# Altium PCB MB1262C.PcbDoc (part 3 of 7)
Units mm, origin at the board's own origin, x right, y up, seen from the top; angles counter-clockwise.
Board outline 208 x 250 mm, 6 copper layers (Top Layer, Layer 2, Layer 3, Layer 4, Layer 5, Bottom Layer), stack 1.596 mm thick; 483 components, 502 nets, 2134 pads, 1709 vias.
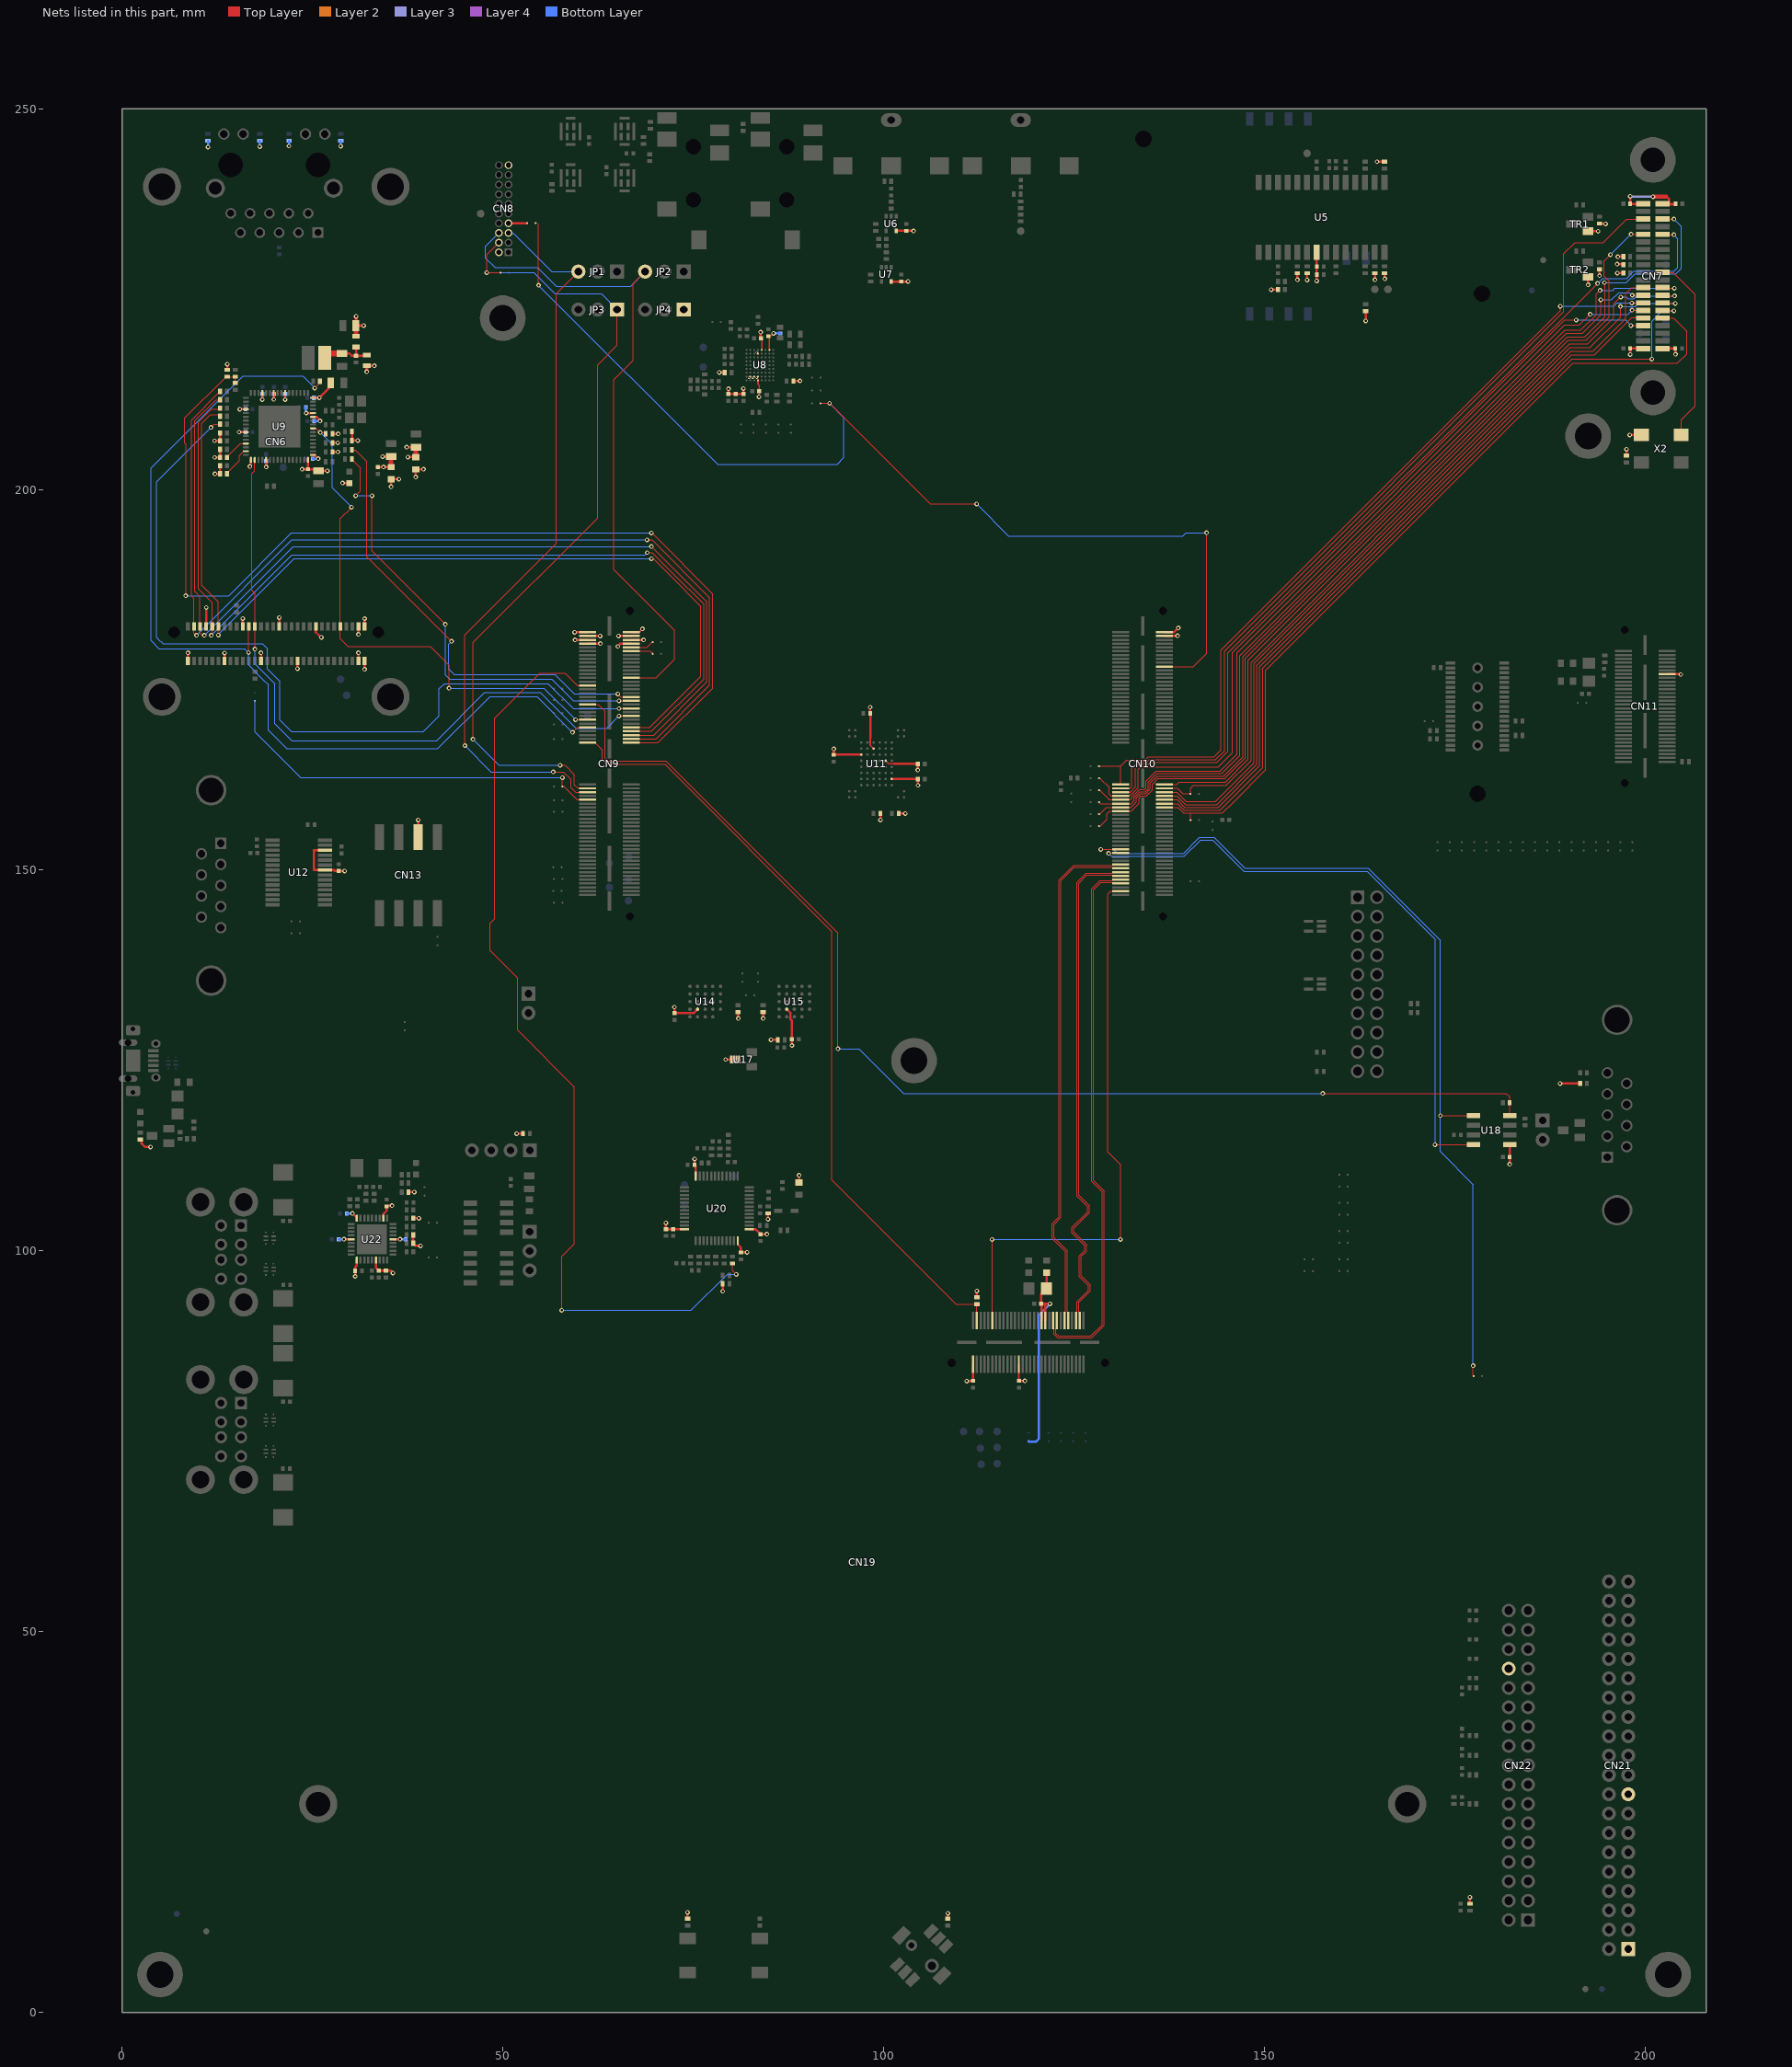
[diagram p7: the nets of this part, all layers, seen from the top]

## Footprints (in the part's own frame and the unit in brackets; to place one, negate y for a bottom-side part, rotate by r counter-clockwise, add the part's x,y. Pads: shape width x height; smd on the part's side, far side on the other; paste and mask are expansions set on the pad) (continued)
MIC_HCLGA_3X4X1_4LD [mm]
  rect 0.4x0.95 smd paste+0 mask+0.05: 1(0.45,-0.675) 2(0.45,0.675) 3(-0.45,0.675) 4(-0.45,-0.675)
  rect 1.3x0.35 smd paste+0 mask+0.05: 5(0,-1.725) 6(0,1.725)
  rect 0.35x2.3 smd paste+0 mask+0.05: 7(1.225,0) 8(-1.225,0)
  silkscreen extent -1.55,-2.05 1.55,2.05, body extent -1.45,-1.95 1.45,1.95, height 1.03
MIRE_PLACE_SMD_0P8MM [mm]
  round 0.8 smd mask+0.2: 1(0,0)
  Top Layer keep-out circle w0.01: c0,0 r0.804
MOD_MB1263 [mm]
  silkscreen extent -55,-8 65,78, body extent -55,-8 65,78, height 9.8
MOS_SOT23 [mm]
  rect 1x1.4 smd mask+0.05: 1(-0.95,-1.1) 2(0.95,-1.1) 3(0,1.1)
  silkscreen extent -1.63,-0.82 1.63,0.82, body extent -1.56,-1.25 1.56,1.25, height 1.1
NPN_SOT23 [mm]
  rect 1x1.4 smd mask+0.05: 1(-0.95,-1.1) 2(0.95,-1.1) 3(0,1.1)
  silkscreen extent -1.63,-0.82 1.63,0.82, body extent -1.56,-1.25 1.56,1.25, height 1.1
OSC_PLE_SM77H-SERIES_7X5_H1P73_4P [mm]
  rect 1.96x1.6 smd mask+0.05: 1(-2.62,-1.8) 2(2.62,-1.8) 3(2.62,1.8) 4(-2.62,1.8)
  silkscreen extent -3.55,-2.55 3.55,2.55, body extent -3.55,-2.55 3.55,2.55, height 2.17
PTH_M1261-3005-N_3P5X6_M3_H14 [mm]
  round 6 hole 3.5 mask+0.05: 1(0,0)
  silkscreen extent -3.25,-3.25 3.25,3.25, body extent -2.5,-2.5 2.5,2.5, height 14
R0402 [mm]
  rect 0.51x0.7 smd mask+0.05: 1(-0.45,0) 2(0.45,0)
  silkscreen extent -0.72,-0.43 0.72,0.43, body extent -0.52,-0.3 0.52,0.3, height 0.4
R0603 [mm]
  rect 0.64x1 smd mask+0.05: 1(-0.7,0) 2(0.7,0)
  silkscreen extent -1.05,-0.58 1.05,0.58, body extent -0.9,-0.5 0.9,0.5, height 0.56
SOLDER-BRIDGE_R0603-0R [mil]
  round 10 smd: 1(-19.68,0) 2(23.62,0)
  Top Layer region: -47.24,-19.68 -47.24,19.69 -15.75,19.69 3.94,0 -15.75,-19.68 -47.24,-19.68
  Top Layer region: -5.91,19.69 13.78,0 -5.91,-19.68 47.24,-19.68 47.24,19.69 -5.91,19.69
  silkscreen extent -50,-23 50,23, body extent -36,-20 36,20, height 22
SWI_WEALTHMETAL_TD-0341_4P [mm]
  rect 1.52x2.16 smd mask+0.05: 1(-2.25,-4.75) 2(-2.25,4.75) 3(2.25,-4.75) 4(2.25,4.75)
  silkscreen extent -3,-3.5 3,3.5, body extent -3,-5.15 3,5.15, height 7.55
SWI_XIEJIA_MT-008A_6P [mm]
  rect 1.8x1.1 smd mask+0.05: 1(-3.1,1.4) 2(-3.1,0) 3(-3.1,-1.4) 4(3.1,1.4) 5(3.1,0) 6(3.1,-1.4)
  rect 2.2x1.4 smd mask+0.05: 7(0,3.75) 8(0,-3.75)
  round 1.5 hole 0.8 unplated mask+0.05: MT1(0,1.9)
  round 1.8 hole 1.1 unplated mask+0.05: MT2(0,-1.9)
  silkscreen extent -3.7,-3.7 3.7,3.7, body extent -3.85,-3.75 3.85,3.75, height 5.2
TP_SMD_1MM [mm]
  round 1 smd mask+0.05: 1(0,0)
  silkscreen extent -0.7,-0.7 0.7,0.7

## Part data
B1: library part MT-008A_M, "Joystick with Hat, Multi Function Switch", Manuf_1="XIEJIA Electronics", Manuf_Part_1=MT-008A
B2: library part SW-PUSH-CMS_BLACK, "Non-Open Push-Button 0.1A 24V", Manuf_1=wealthmetal, Manuf_2=FARNELL, Manuf_Part_1=TD0341X-G01-BLA, Manuf_Part_2=535-930
C1 C2 C4 C5 C6 C7 C8 C9 C11 C12 C13 C15 C16 C18 C25 C27 C29 C30 C33 C34 C36 C40 C43 C49 C50 C53 C55 C56 C57 C58 C61 C62 C63 C64 C65 C66 C67 C70 C71 C72 C73 C74 C75 C78 C82 C83 C84 C87 C88 C89 C90 C91 C92 C93 C94 C95 C96 C99 C101 C103 C104 C105 C106 C113 C117 C119 C120 C121 C122 C123 C124 C125 C126 C127 C128 C129 C130 C131 C132 C133 C134: library part Cap_100nF_X7R_10%_0402, "Capacitor,100nF,16V,X7R,10%,0402,YAGEO", Manuf_1=YAGEO, Manuf_Part_1=CC0402KRX7R7BB104
C3 C17 C23 C24 C31 C35 C38 C39 C41 C97: library part Cap_4.7uF_X5R_20%_6V3_0402, "Capacitor MLCC 4,7µF 20% 6,3V 1,9uF@3,3V X5R 0402", Manuf_1=MURATA, Manuf_Part_1=GRM155R60J475ME87
C10 C14: library part Cap_22nF_X7R_10%_0402, "Capacitor,22nF,16V,X7R,10%,0402,YAGEO", Manuf_1=YAGEO, Manuf_Part_1=CC0402KRX7R7BB223
C19 C21 C42 C44: library part Cap_1uF_X5R_10%_6V3_0402, "Capacitor MLCC 1µF 10% 6,3V 0,4uF@3,3V X5R 0402 MURATA", Manuf_1=MURATA, Manuf_Part_1=GRM155R60J105KE19
C20 C32 C37 C47 C48 C51: library part Cap_22uF_X5R_20%_0805, "Capacitor,22uF,6.3V,X5R,20%,0805,Murata", Manuf_1=MURATA, Manuf_Part_1=GRM21BR60J226ME39L
C22 C26 C28: library part Cap_2.2uF_X5R_10%_0603, "Capacitor,2.2uF,10V, X5R,10%,0603,YAGEO", Manuf_1=YAGEO, Manuf_2=KEMET, Manuf_Part_1=CC0603KRX5R6BB225, Manuf_Part_2=C0603C225K8PACTU
C45 C46: library part Cap_10pF_NPO_5%_0402, "Capacitor,10pF,50V,NPO,5%,0402,YAGEO", Manuf_1=YAGEO, Manuf_Part_1=CC0402JRNPO9BN100
C52 C98: library part Cap_10uF_POL_10%_16V_1206, "Polarized Capacitor,10uF,16V,10%,typeA,AVX", Manuf_1=AVX, Manuf_Part_1=TAJA106K016R
C54 C85 C86: library part Cap_10nF_X7R_10%_0402, "Capacitor,10nF,16V,X7R,10%,0402,YAGEO", Manuf_1=YAGEO, Manuf_Part_1=CC0402KRX7R7BB103
C59: library part Cap_10nF_X7R_10%_0402_1, "Capacitor,10nF,16V,X7R,10%,0402,YAGEO", Manuf_1=YAGEO, Manuf_Part_1=CC0402KRX7R7BB103
C60 C108 C109 C110 C111 C112 C114 C115 C116: library part Cap_100pF_NPO_5%_0402, "Capacitor,100pF,50V,NPO,5%,0402,YAGEO", Manuf_1=YAGEO, Manuf_Part_1=CC0402JRNPO9BN101
C68: library part MCD-00011, "Capacitor, MLCC, 10nF, 16V, X7R, 10%, 0402, T=0.5mm", Manufacturer=YAGEO, Manufacturer_Part_Number=CC0402KRX7R7BB103, Package=C0402
C69: library part Cap_4.7uF_POL_10%_TANA, "Polarized Capacitor,4.7uF,16V,10%,typeA,AVX", Manuf_1=AVX, Manuf_Part_1=TAJA475K016R
C76 C100 C102 C107: library part Cap_220uF_POL_10%_TAJA, "Polarized Capacitor,220uF,10V,10%,AVX", Manuf_1=AVX, Manuf_Part_1=TAJC227K010R
C77: library part Cap_47uF_X5R_20%_0805, "Capacitor,47uF,10V,X5R,20%,0805,MURATA", Manuf_1=MURATA, Manuf_Part_1=GRM21BR61A476ME15K
C79: library part MCD-00095, "Capacitor, MLCC, 1uF, 6V3, X5R, 10%, 0402, T=0,5mm", Manufacturer=MURATA, Manufacturer_Part_Number=GRM155R60J105KE19, Package=C0402
C80 C81: library part Cap_18pF_NPO_5%_0402, "Capacitor,18pF,50V,NPO,5%,0402,YAGEO", Manuf_1=YAGEO, Manuf_Part_1=CC0402JRNPO9BN180
C118: library part Cap_1nF_X7R_10%_0402, "Capacitor,1nF,16V,X7R,10%,0402,YAGEO", Manuf_1=YAGEO, Manuf_Part_1=CC0402KRX7R7BB102
CN1: library part RCJ-013-SMT, "RCA Phono Jack, Right Angle, SMD, White", Manuf_1=JIUBABA, Manuf_2="CUI Inc", Manuf_Part_1=JBB0819100004
CN2: library part RCJ-014-SMT, "RCA Phono Jack, Right Angle, SMD, Yellow", Manuf_1=JIUBABA, Manuf_2="CUI Inc", Manuf_Part_1=JBB0819100002
CN3: library part CON_RJ45_48F_01GYDXNL, "RJ45 (shielded) Ethernet connector with Integral LEDs (green/yellow)", Manuf_1="Yuan Dean Scientific Co Ltd", Manuf_Part_1=48F-01GYDXNL
CN4: library part PJ3028B-3_GR, "Connector Jack Stereo 3.5mm, female SMT, Green (Line output)", Manuf_Part_2=PJ30280-3_GR
CN5: library part PJ3028B-3_GR, "Headset Connector Stereo 3.5mm, female SMT, black", Manuf_Part_1="PJ-3028B-3 4P"
CN6: library part CONN_ERF8_030, "RJ45 (shielded) Ethernet connector with Integral LEDs (green/yellow)", Manuf_1=SAMTEC, Manuf_Part_1=ERF8-30-07.0-L-DV-TR
CN7: library part CLM-120-02-L-D_2_Reverse_for_camera, "Header, 20-Pin, Dual row", Manuf_1=SAMTEC, Manuf_Part_1=CLM-120-02-L-D
CN8: library part "Header 10X2 TH VT 1.27mm_with MB1299", "20 Position Receptacle Connector 0.050\" (1.27mm) Through Hole Vertical Mount", Manuf_1=AMPHEMOL_FCI, Manuf_Part_1=20021311-00020T4LF
CN9 CN10: library part QSH-060-01-L-D-A, "Samtec connector QSH 120p", Manuf_1=SAMTEC
CN11: library part QSH-030-01-F-D-A, "HIGH SPEED SOCKET STRIP, .5mm PITCH, 60 PINS", Manuf_1=SAMTEC
CN12 CN15: library part CONN_DB9_male_3_1634580_2, "9 Positions,,through-hole , Right Angle, Product Series = HD 20, With Mating Connector LockMale", Manuf_1=TYCO, Manuf_Part_1=3-1634580-2
CN13: library part SSM-104-L-DH, "Série SSM, 8 Contact, 2.54 mm, CMS", Manuf_1=SAMTEC
CN14: library part CONN_Header_2x10_Male_JTAG, "Headers 2x10pins CH87 series 2.54mm Male", Manuf_1=CVILUX, Manuf_Part_1=CH87-20-2-V-1-00
CN16: library part 475900001, "USB-MICRO-AB, 47590-0001, SMT, MOLEX", Manuf_1=MOLEX, Manuf_Part_1=47590-0001
CN17: library part "Header 4", "Header, 4-Pin", Manuf_1=Samtec, Manuf_Part_1=TSW-104-07-x-S
CN18 CN20: library part CONN_USB_DUAL_TYPEA, "USB Dual Type A Receptacle 5600 Series.", Manuf_1=CONEXCON, Manuf_2=Cliff, Manuf_Part_1="5600 - 3081", Manuf_Part_2=FCK002A
CN19: library part QSH-030-01-F-D-A_DSI_LCD, "HIGH SPEED SOCKET STRIP, .5mm PITCH, 60 PINS", Manuf_1=SAMTEC, Manuf_Part_1=QSH-030-01-F-D-A
CN21: library part "Header 20x2 male", "Header,20 pin , Dual Row", Manuf_1=Samtec, Manuf_Part_1=TSW-120-07-G-D
CN22: library part MotorControl_connector, "Motor Control connector WINPIN", Manuf_1=WINPIN, Manuf_Part_1=BHFS03-34G01BT1
CN23: library part Smart_card_CN, "Smartcard connector"
D1: library part BAT60JFILM, "BAT60JFILM", Manuf_1=STM
H1 H2 H3 H4 H5: library part "POSITION HOLE C6D3R5"
JP1 JP2 JP3 JP4 JP7: library part "Header 3", "Header, 3-Pin", Manuf_1=Samtec, Manuf_Part_1=TSW-103-07-F-S
JP5 JP6: library part TSW-102-07-x-S, "Connector jumper 1 position", Manuf_1=SAMTEC, Manuf_2=KONTEC, Manuf_Part_2=4711955140470
L1 L2: library part BEAD_100R_2A_0603, "Bead,100R at 100Mhz,2A,0603", Manuf_1=MURATA, Manuf_Part_1=BLM18EG101TN1
L3 L4 L6 L8 L9: library part BEAD_600R_350MA_0603, "Bead,600R,350mA,0603", Manuf_1=Tai-tech, Manuf_2=TDK, Manuf_3=MURATA, Manuf_Part_1=FCM1608KF-601T03, Manuf_Part_2=MPZ1608S300A, Manuf_Part_3=BLM18PG121SN1D
L5: library part BEAD_120R_2A_0603, "Bead,120R at 100Mhz,2A,0603", Manuf_1=MURATA, Manuf_Part_1=BLM18PG121SN1D
L7: library part BEAD_26R_6A_0603_1, "Bead,26R at 100Mhz,6A,0603", Manuf_1=MURATA, Manuf_Part_1=BLM18KG260TN1
LD1: library part LED_green, "LED, Green, 0603", Manuf_1=everlight, Manuf_Part_1=19-213SYGC/S530-E2/TR8
LD2: library part LED_green, "LED, Green", Manuf_1=everlight, Manuf_Part_1=19-213SYGC/S530-E2/TR8
LD3: library part LED_red, "LED, Red, 0603", Manuf_1=everlight, Manuf_Part_1=19-213-R6C-AP1Q2B/3T
LE1: library part Ind_4.7uH_1A_30%, "FIXED IND 4.7UH 1A 180 MOHM 30% SMD", Manuf_1=MURATA, Manuf_Part_1=LQH32PN4R7NN0L
R1 R4 R13 R16 R25 R45 R49 R50 R53 R54 R56 R65 R69 R73 R74 R75 R76 R77 R82 R83 R93 R97 R99 R103 R104 R110 R111 R118 R122 R123 R124 R125 R127 R131 R132 R133 R134 R136: library part Res_0_5%_0402, "Resistor,0R,0402,5%,YAGEO", Manuf_1=YAGEO, Manuf_Part_1=RC0402JR-070RL
R2 R12 R17 R21 R28 R41 R43 R47 R94 R107 R129: library part Res_1K_1%_0402, "Resistor,1K,0402,1%,YAGEO", Manuf_1=YAGEO, Manuf_Part_1=RC0402FR-071KL
R3 R8 R19 R26 R27 R30 R31 R67 R78 R79 R80 R81 R84 R85 R86 R87 R88 R89 R91 R92 R95 R98 R101 R105 R109 R113 R128 R130 R139: library part Res_10K_1%_0402, "Resistor,10K,0402,1%,YAGEO", Manuf_1=YAGEO, Manuf_Part_1=RC0402FR-0710KL
R5 R22 R23 R24 R32 R108 R114 R115 R117 R119 R120 R121 R135: library part Res_100K_1%_0402, "Resistor,100K,0402,1%,YAGEO", Manuf_1=YAGEO, Manuf_Part_1=RC0402FR-07100KL, Manuf_Part_2=RT0402FRE07100KL
R6 R14 R20 R38 R39 R40 R58 R59 R61 R62 R64 R68 R71 R72 R141 R142: library part Res_4K7_1%_0402, "Resistor,4K7,0402,1%,YAGEO", Manuf_1=YAGEO, Manuf_Part_1=RC0402FR-074K7L, Manuf_Part_2=RT0402FRE074K7L
R7: library part Res_75_1%_0402, "Resistor,75,0402,1%,YAGEO", Manuf_1=YAGEO, Manuf_Part_1=RC0402FR-0775RL
R9: library part Res_110_1%_0402, "Resistor,110R,0402,1%,YAGEO", Manuf_1=YAGEO, Manuf_Part_1=RC0402FR-07110RL
R10: library part Res_210_1%_0402, "Resistor,210R,0402,1%,YAGEO", Manuf_1=YAGEO, Manuf_Part_1=RC0402FR-07210RL
R11 R18 R106 R138: library part Res_100_1%_0402, "Resistor,100R,0402,1%,YAGEO", Manuf_1=YAGEO, Manuf_Part_1=RC0402FR-07100RL
R15 R29: library part Res_1M_1%_0402, "Resistor,1M,0402,1%,YAGEO", Manuf_1=YAGEO, Manuf_Part_1=RC0402FR-071ML
R33 R34: library part Res_0_5%_0603, "Resistor,0R,0603,5%,YAGEO", Manuf_1=YAGEO, Manuf_Part_1=RC0603JR-070RL
R35: library part Res_2K2_1%_0402, "Resistor,2K2,0402,1%,YAGEO", Manuf_1=YAGEO, Manuf_Part_1=RC0402FR-072K2L
R36 R37: library part Res_20_1%_0402, "Resistor,20R,0402,1%,YAGEO", Manuf_1=YAGEO, Manuf_Part_1=RC0402FR-0720RL
R42 R46: library part Res_180_1%_0402_1, "Resistor,180R,0402,1%,YAGEO", Manuf_1=YAGEO, Manuf_Part_1=RC0402FR-07180RL
R44 R48 R51 R52 R55: library part Res_22_1%_0402, "Resistor,22R,0402,1%,YAGEO", Manuf_1=YAGEO, Manuf_Part_1=RC0402FR-0722RL
R57: library part Res_2K49_1%_0402, "Resistor,2K49,0402,1%,YAGEO", Manuf_1=YAGEO, Manuf_Part_1=RC0402FR-072K49L
R60 R63 R66: library part Res_1K5_1%_0402, "Resistor,1K5,0402,1%,YAGEO", Manuf_1=YAGEO, Manuf_Part_1=RC0402FR-071K5L
R70 R126 R140 R143: library part Res_510_1%_0402, "Resistor,510R,0402,1%,YAGEO", Manuf_1=YAGEO, Manuf_Part_1=RC0402FR-07510RL
R90: library part MCD-00285, "Resistor,15K,0402,5%,1/16W", Manufacturer=YAGEO, Manufacturer_Part_Number=RC0402JR-0715KL, Package=R0402
R96: library part Res_120_1%_0402, "Resistor,120R,0402,1%,YAGEO", Manuf_1=YAGEO, Manuf_Part_1=RC0402FR-07120RL
R100: library part Res_330_1%_0402, "Resistor,330R,0402,1%,YAGEO", Manuf_1=YAGEO, Manuf_Part_1=RC0402FR-07330RL
R102 R116: library part Res_47K_1%_0402, "Resistor,47K,0402,1%,YAGEO", Manuf_1=YAGEO, Manuf_Part_1=RC0402FR-0747KL
R112: library part Res_12K_1%_0402, "Resistor,12K,0402,1%,YAGEO", Manuf_1=YAGEO, Manuf_Part_1=9C06031A1202FKHFT
R137: library part Res_3K3_1%_0402, "Resistor,3K3,0402,1%,YAGEO", Manuf_1=YAGEO, Manuf_Part_1=RC0402FR-073K3L
SB1 SB4 SB12 SB13 SB14 SB18 SB19 SB20 SB21 SB22 SB23 SB24 SB25 SB26 SB28 SB29 SB30 SB31 SB32 SB33 SB52 SB53 SB55 SB56 SB58 SB61 SB63 SB65 SB66 SB67 SB68 SB69 SB70 SB71 SB72 SB73 SB74 SB75 SB76: library part SB_OFF, "Solder Bridge OFF"
SB2 SB3 SB5 SB6 SB7 SB8 SB9 SB10 SB11 SB15 SB16 SB17 SB27 SB34 SB35 SB36 SB37 SB38 SB39 SB40 SB41 SB42 SB43 SB44 SB45 SB46 SB47 SB48 SB49 SB50 SB51 SB54 SB57 SB59 SB60 SB62 SB77 SB78 SB79 SB80 SB81 SB82: library part SB_ON, "Solder Bridge ON"
SB64: library part MCD-00071, "Solder Bridge ON"
T1: library part 9013-SOT23, "NPN Bipolar Transistor", Manuf_1=NXP, Manuf_Part_1=BSR14
TP1 TP2 TP3 TP4 TP5 TP6 TP7 TP8 TP9 TP10 TP11 TP12 TP13 TP14 TP15 TP16 TP17 TP18 TP19 TP20 TP21 TP22 TP23 TP24 TP25 TP26 TP27 TP28 TP29 TP30: library part "TP 1mm", "Test Point"
TR1 TR2: library part BSN20, "N-channel enhancement mode field-effect transistor", Manuf_1=NXP, Manuf_2=DiodesINc, Manuf_Part_2=BSN20-7
U1 U2 U3 U4: library part MP34DT01TR-M, "MEMS audio sensor, omnidirectional digital microphone", Manuf_1=STM
U5: library part ST8024CDR, "Smartcard interface", Manuf_1=ST
U6 U7: library part 74LVC1G04SE, "Single inverter gate with a standard push-pull output. (1.65V to 5.5V)", Manuf_1="DIODES INC", Manuf_Part_1=74LVC1G04SE-7
U8: library part WM8994ECS/R, "Multi-Channel Audio Hub CODEC for Smartphones", Manuf_1="Cirrus Logic"
U9: library part RTL8211EG, "REALTEK 10/100/1000 GIGABIT Ethernet Transceiver", Manuf_1=REALTEK, Manuf_Part_1=RTL8211EG-VB-CG
U10: library part CONN_Mictor_38_SMT, "Mictor 38 pins Vertical Receptacles 2-5767004-2", Manuf_1=TYCO, Manuf_Part_1=2-5767004-2
U11: library part MT29F8G08ABACAH4, "SLC NAND 8Gb/8bits/8ECC/4K VFBGA 9x11", Manuf_1=MICRON, Manuf_Part_1=MT29F8G08ABACAH4-ITS:C
U12: library part ST3241EBPR, "RS-232 transceiver with auto-power-down", Manuf_1=ST
U13 U16: library part ESDALC6V1W5, "Dual Transil array for ESD protection", Manuf_1=STM, Manuf_Part_1=ESDA5V3L
U14 U15: library part MX25L51245G, "Serial NOR 512Mb/3V BGA", Manuf_1=MACRONIX, Manuf_Part_1=MX25L51245G-XD
U18: library part MCP2562FD, "High-Speed CAN Flexible Data Rate Transceiver", Manuf_1=Microchip, Manuf_Part_1=MCP2562FDT-H/SN
U19: library part ESDCAN24-2BLY, "transient voltage suppressor for ESD protection for CAN bus", Manuf_1=ST
U20: library part STM32L152CCT6, "Multifunction expander", Manuf_1=ST
U21 U23: library part STMPS2252MTR, "Enhanced dual channel power switches 500mA", Manuf_1=ST
U22: library part USB2514B-AEZC, "IC, USB2514B, 4 Port USB 2.0 Hub w/ Battery Chg, QFN36", Manuf_1=SMSC
X1: library part XTAL_25M_NX3225GA, "Surface mount Crystal. Load capacitance: 10pF", Manuf_1=NDK, Manuf_Part_1=NX3225GA-25.000M-EXS00A-CH00343
X2: library part SM7745HEV-24.0M, "SM77H Series 3.3V  CMOS Clock Oscillators", Manuf_1=Pletronics, Manuf_Part_1=SM7745HEV
X3: library part XTAL_24M_7A-24.000MAAE-T, "Crystal, 24.000MHz, 30ppm, 18pF, 7A-24.000MAAE-T", Manuf_1=TXC, Manuf_Part_1=7A-24.000MAAE-T
Z1 Z2 Z3 Z4 Z5: library part FIL_EMIF_USB_2, "Common mode filter with ESD protection for USB2.0 interface", Manuf_1=ST, Manuf_Part_1=ECMF02-4CMX8

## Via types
v1: diameter 0.6, hole 0.3, Top Layer to Bottom Layer, tented both sides, 979 vias
v2: diameter 0.55, hole 0.3, Top Layer to Bottom Layer, tented both sides, 687 vias
v3: diameter 0.3, hole 0.15, Top Layer to Bottom Layer, tented both sides, 31 vias
v4: diameter 0.4, hole 0.2, Top Layer to Bottom Layer, tented both sides, 12 vias

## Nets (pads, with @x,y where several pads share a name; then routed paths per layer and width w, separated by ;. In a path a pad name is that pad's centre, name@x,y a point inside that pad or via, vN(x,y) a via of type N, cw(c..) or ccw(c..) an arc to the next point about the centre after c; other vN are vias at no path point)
1V05_AVDD_GMII: C20.2 C122.2 C124.2 C128.2 R33.1 U9.7 U9.13 U9.59 | length 8.8
  Top Layer w0.3: v1(18.425,211.804) U9.13@18.425,212.675 ; v1(21.425,211.798) U9.7@21.425,212.675 ; U9.59@25.075,209.525 25.523,209.525 26,209.048 v1(26,209) ; C20.2@30.707,221.505 C20.2@30.731,221.482
  Top Layer w0.4: v1(30.746,222.732) 30.746,221.544 C20.2@30.707,221.505 v1(31.724,221.505)
  Top Layer w0.6: R33.1@30.731,220.107 C20.2@30.731,221.482
  Bottom Layer w0.3: v1(18.425,211.804) C124.2@18.425,212.532 ; v1(21.425,211.798) C122.2@21.425,212.532 ; C128.2@25.235,208.978 25.978,208.978 v1(26,209)
1V05_DVDD_GMII: C50.2 C51.2 R34.1 U9.33 U9.48 | length 7.3
  Top Layer w0.25: v1(16.798,202.999) 16.925,203.126 U9.33@16.925,203.875
  Top Layer w0.3: v1(23.643,202.645) C50.2@24.421,202.645 25.585,202.645 C51.2@25.791,202.439 25.796,202.435 v1(26.977,202.435) ; C50.2@24.421,202.745 24.421,203.871 U9.48@24.425,203.875
  Top Layer w0.4: v1(32.133,215.445) R34.1@32.133,216.239 v1(33.136,216.239)
1V05_GMII: C32.2 C33.2 LE1.2 R33.2 R34.2 | length 7
  Top Layer w0.3: C32.2@28.859,217.847 29.864,217.847 30.15,217.561 C33.2@30.73,217.561 ; R33.2@30.73,218.707 C33.2@30.73,217.561 ; R34.2@32.133,217.639 32.054,217.561 C33.2@30.73,217.561
  Top Layer w0.8: LE1.2@26.64,217.278 27.209,217.847 C32.2@28.859,217.847
1V8: C11.1 C12.2 C25.2 C40.2 C103.2 C121.2 CN7.1 CN7.2 CN10.2 CN10.4 CN19.60 R21.1 R28.1 R67.1 U8.D1 U8.D8 U8.G9 X2.4 | length 28
  Top Layer w0.2: v3(83.34,217.985) U8.D8@83.5,217.825 ; U8.D1@83.5,214.325 83.498,214.323 83.498,213.821 83.663,213.656 83.663,213.013 C40.2@83.55,212.9 ; v1(83.65,212.148) C40.2@83.65,212.9 ; v1(85.551,220.484) 85.248,220.181 85.057,220.181 85,220.125 U8.G9@85,218.338 ; U8.G9@85,218.338 85.007,218.332 U8.G9@85,218.325 U8.G9@85,218.338
  Top Layer w0.3: C25.2@84.85,220.125 C25.2@85,220.125 ; v1(85.551,220.484) v1@85.562,220.473 ; v1@110.965,82.938 110.977,82.95 C103.2@111.75,82.95 ; C103.2@111.746,83.003 111.75,83.007 CN19.60@111.75,85.13 ; CN10.4@136.87,180.75 136.873,180.753 v1@138.591,180.753 ; CN10.2@137.012,181.264 138.134,181.264 138.395,181.525 138.399,181.525 138.694,181.82 v1(138.694,181.818) ; v1(138.594,180.774) 138.612,180.774 138.622,180.765 v1@138.609,180.753 ; v1(196.297,229.578) 197.047,229.578 R21.1@197.125,229.5 ; v1(196.324,228.415) 197.115,228.415 R28.1@197.125,228.425 ; R67.1@197.525,204.45 197.544,204.469 v1(197.544,205.272) ; v1(197.974,207.151) X2.4@199.479,207.151 ; v1(198.025,238.495) C11.1@198.025,237.5 CN7.1@199.725,237.5 ; CN7.2@202.275,237.5 CN7.2@203.136,237.5 ; 202.792,238.436 203.136,238.093 CN7.2@203.136,237.5 ; v1@138.591,180.753 v1@138.609,180.753 ; v1@138.591,180.753 138.582,180.762 138.591,180.771 v1@138.609,180.753 ; CN7.2@203.136,237.5 203.136,237.487 203.176,237.447 203.922,237.447 C12.2@203.975,237.5 CN7.2@203.136,237.5
  Top Layer w0.5: v1(201.011,238.436) 202.792,238.436
  Layer 4 w0.3: v1(196.297,229.578) v1@196.324,229.551
  Layer 3 w0.3: v1(198.025,238.495) 198.083,238.436 v1(201.011,238.436)
  Bottom Layer w0.3: v1(85.551,220.484) 86.391,220.484 C121.2@86.45,220.425
  other v1: 110.922,82.911
2V8: C29.1 C30.1 CN7.39 CN7.40 CN9.2 CN9.4 CN9.6 CN9.8 R14.2 R20.2 TR1.1 TR2.1 | length 15.8
  Top Layer w0.3: v1(65.098,179.379) 65.469,179.75 CN9.8@66.87,179.75 ; v1(65.187,180.75) CN9.4@66.87,180.75 ; CN9.6@66.87,180.25 v1(68.489,180.25) ; CN9.2@66.87,181.25 67.893,181.25 v1(68.33,181.687) ; v1(192.5,226.859) TR2.1@192.5,227.9 ; TR1.1@192.5,233.9 v1(193.816,233.9) ; v1(193.995,228.085) 194,228.091 R20.2@194,228.9 ; R14.2@194,234.925 194.047,234.878 v1(194.803,234.878) ; v1(198.026,217.702) v1(198.026,217.702) C30.1@198.025,218.5 CN7.39@199.725,218.5 ; CN7.40@202.275,218.5 202.293,218.518 C29.1@203.941,218.518 203.941,217.773 v1(203.973,217.741)
  Layer 3 w0.3: v1@194.793,234.878 v1(194.803,234.878)
3V3: C13.1 C15.1 C17.2 C18.1 C27.2 C41.2 C42.2 C43.2 C55.2 C56.2 C57.2 C58.2 C65.1 C66.2 C67.2 C73.2 C75.2 C84.2 C88.2 C89.2 C90.2 C91.2 C94.2 C96.2 C97.2 C104.2 C132.2 C133.2 C134.2 CN6.1 CN6.8 CN6.13 CN6.20 CN6.25 CN6.32 CN6.37 CN6.44 CN6.57 CN6.58 CN6.59 CN6.60 CN8.2 CN8.19 CN9.1 CN9.3 CN9.5 CN9.7 CN11.47 CN13.5 CN19.36 CN21.1 CN21.17 CN22.28 JP4.1 L1.2 L2.2 L6.1 R6.2 R19.1 R22.2 R23.2 R26.1 R27.1 R31.1 R32.1 R40.1 R43.2 R84.2 R85.2 R87.1 R88.1 R90.1 R94.1 R99.2 R100.2 R109.1 R113.1 R115.2 R119.2 R120.2 R129.2 R130.2 R137.2 R138.1 R139.1 U5.21 U6.5 U7.5 U8.B2 U8.C2 U8.D2 U8.E9 U11.D3 U11.G4 U11.H8 U11.J6 U12.22 U12.26 U14.B4 U15.B4 U17.3 U18.5 U20.1 U20.24 U20.36 U20.48 U22.5 U22.10 U22.15 U22.23 U22.29 U22.36 | length 140.1
  Top Layer w0.2: v3@82.375,214.7 U8.B2@82.5,214.825 ; v3(83.34,214.665) U8.D2@83.5,214.825 ; U8.E9@84,218.325 C27.2@84,219.75 ; C56.2@93.456,165.167 C56.2@93.464,165.175 ; C55.2@98.23,170.65 98.198,170.618 C55.2@98.25,170.566 ; 98.25,167.442 98.25,166.4 U11.J6@98.675,165.975 ; U11.G4@100.275,164.375 100.659,163.991 101.35,163.991
  Top Layer w0.3: R100.2@2.384,114.647 2.56,114.471 2.56,114.125 3.037,113.648 v1(3.738,113.648) ; CN6.1@8.65,177.5 8.658,177.508 v1(8.658,178.562) ; CN6.8@11.05,182 11.049,182.001 11.066,182.019 v1(11.066,184.488) ; CN6.13@13.45,177.5 13.458,177.508 v1(13.458,178.508) ; CN6.20@15.85,182 15.859,182.009 v1(15.859,183.046) ; v1(18.239,178.539) 18.239,177.511 CN6.25@18.25,177.5 ; CN6.32@20.65,182 20.66,182.01 v1(20.66,183.161) ; CN6.37@23.05,177.5 23.053,177.497 v1(23.053,176.47) ; CN6.44@25.45,182 25.446,181.996 25.446,181.25 26.12,180.576 v1(26.177,180.576) ; U12.26@26.65,152.625 26.636,152.611 25.176,152.611 25.176,150.025 U12.22@26.65,150.025 26.662,150.037 27.824,150.037 27.964,149.898 C65.1@28.481,149.898 ; C65.1@28.416,149.892 28.517,149.791 28.623,149.897 v1(29.237,149.897) ; v1(29.143,101.55) U22.5@30.075,101.55 ; v1(30.267,104.93) 30.825,104.371 U22.36@30.825,104.3 ; v1(30.608,96.673) 30.608,97.898 30.825,98.115 U22.10@30.825,98.8 ; v1(31.048,180.963) 31.048,181.998 CN6.58@31.05,182 ; CN6.57@31.05,177.5 v1(31.05,178.545) ; v1(31.846,183.033) 31.846,182.032 31.864,182.014 CN6.60@31.85,182 ; v1(31.85,176.385) CN6.59@31.85,177.5 ; U22.15@33.325,98.8 33.325,97.835 C96.2@33.725,97.435 35.243,97.435 v1(35.568,97.11) ; U22.29@34.325,104.3 34.325,104.865 34.735,105.275 C84.2@34.735,105.862 34.796,105.802 34.947,105.952 v1(35.461,105.952) ; v1(35.341,200.341) L2.2@35.341,201.339 v1(36.359,201.339) ; U22.23@35.575,101.55 v1(36.518,101.55) ; R109.1@37.625,107.736 v1(38.379,107.736) ; R119.2@38.256,102.105 R120.2@38.256,101.005 38.555,100.706 39.158,100.706 v1(39.189,100.676) ; R115.2@38.256,104.305 v1(38.984,104.305) ; v1(38.56,201.631) L1.2@38.56,202.636 v1(39.586,202.636) ; CN13.5@38.895,154.35 v1(38.895,156.605) ; v1(51.814,115.42) R99.2@52.647,115.42 ; v1(59.429,181.25) CN9.1@61.13,181.25 ; v1(59.496,180.244) 59.502,180.25 CN9.5@61.13,180.25 ; CN9.7@61.13,179.75 v1(62.818,179.75) ; CN9.3@61.13,180.75 v1(62.77,180.75) ; v1(71.425,103.687) C88.2@71.425,102.875 C89.2@72.375,102.875 72.4,102.85 U20.36@73.85,102.85 ; C66.2@72.538,131.225 75.05,131.225 U14.B4@75.575,131.75 ; C66.2@72.538,131.237 v1(72.538,132.034) ; R139.1@74.25,12.325 v1(74.25,13.164) ; v1(75.175,112.098) C75.2@75.175,111.3 75.35,111.125 U20.24@75.35,109.85 ; v1(78.41,215.35) R40.1@79.125,215.35 ; v1(78.86,94.709) R129.2@78.86,95.698 ; v1(79.25,125.15) U17.3@80.5,125.15 ; v1(79.627,213.203) 79.627,212.575 C41.2@79.595,212.543 C43.2@81.595,212.543 v1(81.595,213.242) ; U20.48@80.85,101.35 80.85,100.869 81.27,100.449 C91.2@81.27,99.824 v1(82.08,99.824) ; R88.1@80.881,131.37 80.881,130.582 v1(80.913,130.549) ; U20.1@82.35,102.85 83.198,102.85 C90.2@83.837,102.21 v1(84.681,102.21) ; v1(83.864,220.637) 83.864,219.94 83.837,219.913 C27.2@84,219.75 ; v1(84.187,130.548) R87.1@84.187,131.37 ; v1(84.825,104.176) R113.1@84.825,104.95 ; v1(85.225,127.717) R90.1@86.107,127.717 ; U15.B4@87.275,131.75 87.769,131.256 87.769,130.43 87.958,130.242 87.958,127.833 C67.2@87.95,127.825 v1(87.95,126.99) ; R43.2@88.161,214.22 88.982,214.22 v1(89.018,214.256) ; L6.1@88.9,109 v1(88.9,109.94) ; C56.2@93.456,165.167 v1(93.456,165.923) ; C56.2@93.464,165.175 U11.H8@97.075,165.175 ; C55.2@98.23,170.65 v1(98.23,171.407) ; 98.25,167.442 C55.2@98.25,170.566 ; v1(99.575,156.592) R84.2@99.575,157.45 ; U7.5@101,227.3 103.21,227.3 v1(103.222,227.312) ; U11.D3@101.075,161.975 101.404,161.975 101.406,161.973 104.477,161.973 C58.2@104.5,161.95 ; 101.35,163.991 104.459,163.991 C57.2@104.5,163.95 104.5,163.16 v1(104.481,163.141) ; U6.5@101.65,233.95 103.925,233.95 v1(103.937,233.938) ; R85.2@101.975,157.45 v1(102.861,157.45) ; v1(104.502,161.14) C58.2@104.502,161.95 ; R138.1@108.426,12.336 v1(108.426,13.033) ; R130.2@112.25,93.925 v1@112.25,94.675 ; CN19.36@117.75,85.13 117.75,83.027 C104.2@117.812,82.965 ; C104.2@117.816,82.984 117.863,82.938 v1(118.546,82.938) ; v1(150.898,226.226) 150.921,226.25 R31.1@151.775,226.25 ; R22.2@154.325,228.4 154.325,227.548 v1(154.334,227.538) ; R23.2@155.6,228.4 155.6,227.524 v1(155.615,227.509) ; U5.21@156.865,231.135 156.875,231.125 156.875,227.387 v1(156.866,227.378) ; v1(163.298,222.12) R32.1@163.298,223.405 ; R26.1@164.5,228.4 164.5,227.531 v1(164.506,227.526) ; v1(164.776,243.032) 164.784,243.025 R6.2@165.75,243.025 ; R27.1@165.75,228.4 165.818,228.468 v1(165.818,227.662) ; R137.2@176.98,14.285 v1(176.98,15.146) ; U18.5@182.2,113.97 v1(182.2,111.388) v1@182.257,111.332 ; v1(188.81,122.005) 188.816,122 R94.1@191.45,122 ; v1(196.388,230.558) 196.406,230.575 R19.1@197.125,230.575 ; CN11.47@202.87,175.75 202.875,175.755 204.611,175.755 v1(204.67,175.695)
  Layer 2 w0.3: v1(163.298,222.12) v1@163.311,222.107
  Layer 3 w0.3: v1(80.913,130.549) v1@80.914,130.548 ; v1(104.481,163.141) v1@104.502,163.12 ; v1(154.334,227.538) v1@154.363,227.509 ; v1@164.776,243.017 v1(164.776,243.032)
  Bottom Layer w0.3: C134.2@28.45,101.55 v1(29.143,101.55) ; C132.2@29.517,104.935 30.262,104.935 v1(30.267,104.93) ; v1(36.518,101.55) C133.2@37.25,101.55
  other v1: 112.251,94.746
  other v3: 82.34,214.665 82.84,214.665
3V3_AVDD_GMII: C48.2 C49.2 C123.2 C126.2 L2.1 U9.10 U9.60 | length 7.5
  Top Layer w0.3: v1(19.925,211.811) U9.10@19.925,212.675 ; v1(24.18,210.029) 24.185,210.025 U9.60@25.075,210.025 ; C49.2@33.605,202.917 C49.2@33.598,202.923 34.321,202.923 v1(34.337,202.939) L2.1@35.341,202.939 ; v1(34.211,204.295) C48.2@35.342,204.295 C48.2@35.341,204.294
  Top Layer w0.6: L2.1@35.341,202.939 C48.2@35.341,204.294
  Bottom Layer w0.3: v1(19.925,211.811) C123.2@19.925,212.532 ; C126.2@24.135,210.794 24.135,210.074 v1(24.18,210.029)
3V3_DVDD_GMII: C37.2 C47.2 C125.2 C127.2 C129.2 C130.2 C131.2 L1.1 LD1.1 R38.2 R58.2 R59.2 R60.2 R61.2 R62.2 R63.2 R64.2 R66.2 R68.2 R71.2 R72.2 R140.2 R141.1 R142.1 R143.2 U9.20 U9.26 U9.37 U9.49 U9.64 | length 28.3
  Top Layer w0.3: v1(12.152,206.375) R62.2@12.875,206.375 R59.2@12.875,207.4 R59.2@12.875,207.45 ; v1(12.161,204.2) R68.2@12.875,204.2 R64.2@12.875,205.275 ; v1(12.203,202.05) R72.2@12.875,202.05 R71.2@12.875,203.125 ; R38.2@13.825,215.7 v1(13.825,216.433) ; v1(15.376,207.525) U9.26@16.275,207.525 ; v1(15.453,210.537) 15.464,210.525 U9.20@16.275,210.525 ; v1(18.925,202.961) U9.37@18.925,203.875 ; U9.49@25.075,204.525 25.247,204.525 v1(25.746,204.026) ; U9.64@25.075,212.025 25.085,212.035 v1(25.907,212.035) 27.402,213.529 C37.2@27.402,213.971 ; R66.2@27.637,204.925 v1(28.343,204.925) ; R63.2@27.637,206.116 v1(28.339,206.116) ; R60.2@27.637,207.306 28.375,207.306 v1(28.384,207.297) ; v1(28.972,200.838) LD1.1@29.842,200.838 ; R58.2@30.187,207.628 R61.2@30.187,206.413 v1(30.961,206.413) ; v1(37.394,205.557) C47.2@38.588,205.557 C47.2@38.56,205.529 ; v1(37.533,204.236) L1.1@38.56,204.236
  Top Layer w0.6: L1.1@38.56,204.236 C47.2@38.56,205.529
  Bottom Layer w0.3: v1(11.285,244.945) R142.1@11.285,245.773 ; v1(15.376,207.525) C129.2@16.225,207.525 ; v1(15.453,210.537) 16.213,210.537 C127.2@16.225,210.525 ; v1(18.078,245.014) 18.078,245.728 18.067,245.739 18.099,245.77 R143.2@18.096,245.773 ; v1(18.925,202.961) 18.935,202.971 C130.2@18.935,203.731 ; v1(21.929,245.087) R141.1@21.929,245.78 ; C131.2@25.055,204.023 25.744,204.023 v1(25.746,204.026) ; C125.2@25.206,212.028 25.9,212.028 v1(25.907,212.035) ; v1(28.722,245.085) R140.2@28.722,245.78
5V_STI: C98.1 C101.2 CN19.21 CN19.23 L9.2 SB82.2 | length 29.8
  Top Layer w0.3: CN19.23@120.75,90.87 120.75,93.009 C101.2@120.684,93.075 ; CN19.21@121.25,90.87 121.25,93.073 121.252,93.075 ; 121.261,93.084 121.252,93.075 ; L9.2@121.4,97.054 C98.1@121.4,95.075 ; C98.1@121.408,95.084 C98.1@121.4,95.075 ; v1@121.847,93.075 121.252,93.075 ; C101.2@120.684,93.075 C101.2@120.675,93.075 120.675,94.351 C98.1@121.4,95.075 ; C101.2@120.684,93.075 121.252,93.075
  Bottom Layer w0.3: SB82.2@119.05,75.025 119.05,74.945 119.973,74.945 120.381,75.353 120.381,91.582 v1@121.838,93.039
  other v1: 121.851,93.076
AN0: R68.1 U9.29 | length 3.3
  Top Layer w0.1: R68.1@13.775,204.2 13.775,204.242 15.558,206.025 U9.29@16.275,206.025
ANA0: CN9.10 SB12.2 | length 3.1
  Top Layer w0.1: CN9.10@66.87,179.25 68.907,179.25 69.608,179.951 SB12.2@69.693,179.951
ANA1: CN9.12 SB13.2 | length 3
  Top Layer w0.1: CN9.12@66.87,178.75 69.357,178.75 SB13.2@69.693,178.413
ANTI_TAMP2: CN9.29 R127.1 | length 125.1
  Top Layer w0.1: v1(57.741,92.211) 57.741,99.281 59.381,100.921 59.381,121.544 51.934,128.991 51.934,135.849 48.319,139.464 48.319,143 48.919,143.6 48.919,169.951 54.847,175.878 58.179,175.878 59.807,174.25 CN9.29@61.13,174.25 ; R127.1@80.16,98.373 80.16,97.431 v1(80.649,96.942)
  Bottom Layer w0.1: v1@57.749,92.217 57.756,92.223 74.747,92.223 79.465,96.942 v1(80.649,96.942)
CAMERA_CLK: CN7.20 X2.3 | length 24.7
  Top Layer w0.13: CN7.20@202.275,228.5 202.289,228.486 203.651,228.486 206.573,225.564 206.573,210.98 204.72,209.127 X2.3@204.72,207.15
CAN1_RX: CN10.97 U18.4 | length 82.9
  Top Layer w0.1: v1(129.54,152.21) 129.621,152.291 131.089,152.291 CN10.97@131.13,152.25 ; v1(172.4,113.97) U18.4@177.45,113.97
  Bottom Layer w0.1: v1(129.54,152.21) 129.929,151.821 139.487,151.821 141.608,153.943 143.231,153.943 147.333,149.841 163.478,149.841 172.41,140.91 v1@172.41,114.01
CAN1_TX: CN10.95 SB76.2 U18.1 | length 117.3
  Top Layer w0.1: v1(128.522,152.721) 131.101,152.721 CN10.95@131.13,152.75 ; v1(173.1,117.78) U18.1@177.45,117.78 ; v1(177.392,84.94) 177.392,83.664 SB76.2@177.465,83.591 SB76.2@177.45,83.577
  Bottom Layer w0.1: v1(128.522,152.721) 130.172,152.721 130.679,152.214 139.379,152.214 141.478,154.313 143.386,154.313 147.43,150.269 163.64,150.269 173.1,140.809 173.1,113.044 177.392,108.752 v1(177.392,84.94)
CAN_STBY: CN9.39 R95.2 U18.8 | length 157.4
  Top Layer w0.1: CN9.39@61.13,171.75 62.541,171.75 63.425,170.866 63.425,164.675 63.728,164.373 71.394,164.373 94.013,141.754 v1(94.013,126.564) ; v1(157.641,120.702) 181.757,120.702 182.2,120.259 U18.8@182.2,117.78
  Bottom Layer w0.1: v1(94.013,126.564) 96.743,126.564 102.605,120.703 107.186,120.703 ; 107.186,120.702 v1(157.641,120.702)
CLK125: CN6.22 CN9.51 R44.1 | length 127.2
  Top Layer w0.1: v1(16.624,178.572) 16.624,181.867 16.703,181.947 CN6.22@16.65,182 ; v1(25.299,213.302) 25.329,213.302 25.805,213.778 25.805,213.994 R44.1@25.994,214.182 ; v1(59.162,168.094) 59.805,168.737 61.117,168.737 CN9.51@61.13,168.75
  Bottom Layer w0.1: 3.798,180.831 3.798,202.804 15.869,214.875 23.725,214.875 v1(25.299,213.302) ; 3.802,180.831 3.802,180.142 4.85,179.094 16.103,179.094 v1(16.624,178.572) 16.624,176.941 18.391,175.175 18.563,175.002 ; v1@16.624,178.62 16.638,178.606 v1@16.638,178.572 ; 18.558,174.996 19.202,174.352 19.202,168.391 21.634,165.959 41.468,165.959 48.305,172.795 54.46,172.795 v1(59.162,168.094)
COL_MODE: R72.1 U9.31 | length 4.2
  Top Layer w0.1: R72.1@13.775,202.05 13.775,202.15 15.428,203.803 15.428,204.463 15.99,205.025 U9.31@16.275,205.025
DCMI_D0: CN7.23 CN10.68 | length 101
  Top Layer w0.13: CN10.68@136.87,159.75 138.513,159.75 139.629,158.634 143.73,158.634 149.024,163.928 149.024,176.905 190.25,218.13 193.134,218.13 197.457,222.453 197.457,225.725 198.242,226.51 199.715,226.51 CN7.23@199.725,226.5
DCMI_D1: CN7.24 CN10.71 SB28.2 | length 115.2
  Top Layer w0.13: SB28.2@128.283,158.933 128.466,158.75 CN10.71@131.13,158.75 132.494,158.75 132.879,159.135 132.879,159.502 133.691,160.314 134.375,160.314 134.744,160.684 134.744,161.573 135.869,162.697 144.392,162.697 146.773,165.078 146.773,178.201 189.488,220.915 191.537,220.915 193.565,222.943 193.565,225.625 v1(194.08,226.14) ; CN7.24@202.275,226.5 202.365,226.41 v1(203.824,226.41)
  Bottom Layer w0.13: v1(194.08,226.14) 195.739,226.14 196.01,226.41 v1(203.824,226.41)
DCMI_D2: CN7.25 CN10.73 SB30.2 | length 109.6
  Top Layer w0.13: SB30.2@128.283,157.354 128.331,157.354 129.227,158.25 CN10.73@131.13,158.25 132.446,158.25 133.189,158.993 133.189,159.488 133.767,160.065 134.451,160.065 135.018,160.632 135.018,161.434 135.957,162.374 144.671,162.374 147.196,164.899 147.196,178.08 189.624,220.508 191.739,220.508 194.164,222.933 194.149,222.948 v1(194.149,224.899) ; v1(198.307,225.491) 199.716,225.491 CN7.25@199.725,225.5
  Bottom Layer w0.13: v1(194.149,224.899) 195.571,224.899 196.507,225.835 197.934,225.835 198.278,225.491 v1(198.307,225.491)
DCMI_D3: CN7.26 CN10.64 SB26.2 | length 105.3
  Top Layer w0.13: CN10.64@136.87,160.75 136.918,160.798 138.536,160.798 139.307,160.026 SB26.2@140.293,160.026 140.293,160.792 140.645,161.144 144.982,161.144 148.249,164.411 148.249,177.292 180.846,209.89 190.083,219.127 192.428,219.127 195.877,222.575 195.877,224.362 v1(196.79,225.275) ; CN7.26@202.275,225.5 202.362,225.413 v1(203.851,225.413)
  Bottom Layer w0.13: v1(196.79,225.275) 197.501,225.275 197.75,225.026 198.499,225.026 198.886,225.413 v1(203.851,225.413)
DCMI_D4: CN7.27 CN10.61 SB21.2 | length 108
  Top Layer w0.13: SB21.2@128.283,163.672 131.13,163.672 ; CN10.61@132.045,161.25 CN10.61@131.13,161.25 131.13,163.672 ; v1(188.838,224.052) 188.838,223.474 144.278,178.914 144.278,165.791 143.379,164.891 134.762,164.891 134.324,164.453 131.911,164.453 131.13,163.672 ; v1(198.242,224.472) 199.697,224.472 CN7.27@199.725,224.5
  Bottom Layer w0.13: v1(188.838,224.052) 195.848,224.052 196.3,224.503 198.21,224.503 v1(198.242,224.472)
DCMI_D5: CN7.28 CN10.66 | length 104.9
  Top Layer w0.13: CN10.66@136.87,160.25 138.472,160.25 139.71,159.012 143.552,159.012 148.65,164.11 148.65,177.125 190.154,218.629 192.749,218.629 196.743,222.623 v1(196.743,224.038) ; CN7.28@202.275,224.5 202.369,224.406 v1(203.941,224.406)
  Bottom Layer w0.13: v1(196.743,224.038) 196.775,224.007 198.705,224.007 199.104,224.406 v1(203.941,224.406)
DCMI_D6: CN7.29 CN10.69 SB24.2 | length 107.1
  Top Layer w0.13: SB24.2@128.283,160.513 128.355,160.513 129.618,159.25 CN10.69@131.13,159.25 ; CN10.69@131.131,159.251 132.418,159.251 132.575,159.408 132.575,159.595 133.575,160.596 134.331,160.596 134.454,160.718 134.454,161.708 135.778,163.033 144.162,163.033 146.383,165.254 146.383,178.544 189.412,221.572 191.353,221.572 v1(192.779,222.997) ; v1(198.26,223.54) 199.679,223.54 199.682,223.543 CN7.29@199.725,223.5
  Bottom Layer w0.13: v1(192.779,222.997) 197.717,222.997 v1(198.26,223.54)
DCMI_D7: CN7.30 CN10.72 | length 106.4
  Top Layer w0.13: CN10.72@136.87,158.75 138.59,158.75 139.451,157.889 144.166,157.889 149.796,163.519 149.796,176.56 190.358,217.122 v1(200.852,217.122) ; CN7.30@202.275,223.5 202.312,223.463 v1(203.752,223.463)
  Bottom Layer w0.13: v1(200.852,217.122) 200.852,222.102 202.213,223.463 v1(203.752,223.463)
DCMI_D8: CN7.9 CN10.62 | length 105.6
  Top Layer w0.13: CN10.62@136.87,161.25 138.483,161.25 138.816,161.583 144.883,161.583 147.883,164.583 147.883,177.539 189.918,219.574 192.223,219.574 195.276,222.627 195.276,227.324 194.609,227.99 194.609,229.989 v1(195.428,230.807) ; v1(198.141,233.504) 199.721,233.504 CN7.9@199.725,233.5
  Bottom Layer w0.13: v1(195.428,230.807) 198.125,233.504 v1(198.141,233.504)
DCMI_D9: CN7.10 CN10.65 | length 116.9
  Top Layer w0.13: CN10.65@131.13,160.25 132.372,160.25 133.081,160.959 133.081,163.35 133.626,163.895 134.823,163.895 135.065,164.137 143.765,164.137 145.226,165.597 145.226,178.549 192.889,226.212 v1(193.725,227.048) v1@193.588,227.185 ; CN7.10@202.275,233.5 202.333,233.442 v1(203.754,233.442)
  Bottom Layer w0.13: v1(193.725,227.048) 194.39,227.713 197.536,227.713 198.478,228.655 203.795,228.655 204.279,229.139 204.279,232.917 v1(203.754,233.442)
DCMI_D10: CN7.5 CN10.63 | length 113.1
  Top Layer w0.13: CN10.63@131.13,160.75 132.38,160.75 132.562,160.931 132.562,163.373 133.347,164.158 134.538,164.158 134.875,164.496 143.552,164.496 144.752,165.696 144.752,178.792 189.303,223.343 189.303,230.925 190.803,232.426 194.498,232.426 197.573,235.5 CN7.5@199.725,235.5
DCMI_D11: CN7.6 CN10.75 SB33.2 | length 126.8
  Top Layer w0.13: SB33.2@128.283,155.774 128.414,155.774 129.317,156.677 129.317,157.374 129.693,157.75 CN10.75@131.13,157.75 132.499,157.75 133.512,158.763 133.512,159.486 133.804,159.778 134.525,159.778 135.304,160.556 135.304,161.291 136.039,162.026 144.789,162.026 147.513,164.75 147.513,177.796 189.754,220.036 192.039,220.036 194.697,222.694 194.697,227.103 v1(194.65,227.15) ; CN7.6@202.275,235.5 202.279,235.504 v1(203.754,235.504)
  Bottom Layer w0.13: v1(194.65,227.15) 197.476,227.15 198.615,228.289 204.025,228.289 204.758,229.022 204.758,234.499 v1(203.754,235.504)
DCMI_HSYNC: CN7.31 CN10.70 | length 97.5
  Top Layer w0.13: CN10.70@136.87,159.25 138.529,159.25 139.536,158.243 143.926,158.243 149.392,163.709 149.392,176.73 190.304,217.643 193.361,217.643 198.25,222.532 199.693,222.532 CN7.31@199.725,222.5
DCMI_PIXCK: CN7.33 CN10.67 SB22.2 | length 108.2
  Top Layer w0.13: SB22.2@128.283,162.093 128.376,162.093 129.593,160.876 129.593,160.023 129.867,159.75 CN10.67@131.13,159.75 131.19,159.81 132.397,159.81 133.431,160.844 133.431,163.266 133.749,163.584 143.909,163.584 145.781,165.456 145.781,178.581 189.434,222.234 v1(190.925,222.234) ; v1(198.121,221.528) 199.665,221.528 199.681,221.544 CN7.33@199.725,221.5
  Bottom Layer w0.13: v1(190.925,222.234) 197.416,222.234 v1(198.121,221.528)
DCMI_VSYNC: CN7.32 CN10.74 SB32.2 | length 109.3
  Top Layer w0.13: CN10.74@136.87,158.25 138.659,158.25 139.397,157.512 140.296,157.512 ; SB32.2@140.303,156.582 140.303,157.505 140.296,157.512 ; CN7.32@202.275,222.5 202.292,222.483 203.702,222.483 205.445,220.741 205.445,217.819 204.198,216.572 190.47,216.572 150.161,176.264 150.161,163.199 145.894,158.931 144.475,157.512 140.296,157.512
DFSDM_CKOUT: CN8.4 CN9.63 JP3.1 SB2.1 | length 108.3
  Top Layer w0.1: v1(46.091,167.192) 46.091,179.897 62.439,196.245 62.439,216.367 64.995,218.923 JP3.1@64.995,223.607 ; v1@47.897,228.462 47.899,228.46 SB2.1@49.697,228.46 ; v1@47.899,228.465 47.899,230.822 CN8.4@49.482,232.406 CN8.4@49.46,232.428 ; v1(57.523,163.787) 58.162,163.787 59.403,162.545 59.403,161.194 59.847,160.75 CN9.63@61.13,160.75
  Bottom Layer w0.1: v1(46.091,167.192) 49.496,163.787 v1(57.523,163.787) ; v1(47.904,228.463) 54.076,228.462 54.8,227.738 56.865,225.673 62.929,225.673 JP3.1@64.995,223.607
DFSDM_D5: CN10.20 SB1.1 SB6.1 | length 146.4
  Top Layer w0.1: 54.6,234.9 54.7,234.8 v1(54.7,226.8) ; SB6.1@91.7,211.3 v1(92.9,211.3) 106.1,198.1 v1(112.2,198.1) ; CN10.20@136.87,176.75 140.65,176.75 142.4,178.5 v1(142.4,194.3)
  Bottom Layer w0.1: v1(54.7,226.8) 78.2,203.3 93.9,203.3 94.8,204.2 94.8,209.4 v1(92.9,211.3) ; v1(112.2,198.1) 116.4,193.9 139.3,193.9 139.7,194.3 v1(142.4,194.3)
DFSDM_DATA1: CN8.6 CN9.26 JP2.3 | length 90.1
  Top Layer w0.13: CN9.26@66.87,175.25 70.101,175.25 72.563,177.712 72.563,181.51 64.6,189.473 64.6,214.381 67.134,216.915 67.134,227.057 JP2.3@68.684,228.607
  Bottom Layer w0.13: CN8.6@49.482,233.676 47.746,231.94 47.746,230.374 48.974,229.146 54.538,229.146 57.02,226.664 66.789,226.664 JP2.3@68.696,228.571 ; JP2.3@68.684,228.607 JP2.3@68.684,228.77
DFSDM_DATA3: CN8.5 CN9.65 JP1.3 | length 98.9
  Top Layer w0.1: v1(45.027,166.366) 45.027,180.917 57.004,192.893 57.004,225.697 JP1.3@59.915,228.607 ; v1(56.629,162.915) 57.94,162.915 58.953,161.902 58.953,160.856 59.559,160.25 CN9.65@61.13,160.25
  Bottom Layer w0.1: v1(45.027,166.366) 48.479,162.915 v1(56.629,162.915) ; CN8.5@50.723,233.64 51.41,233.64 56.443,228.607 JP1.3@59.915,228.607
DFSDM_DATA5: CN8.7 SB1.2 | length 2.4
  Top Layer w0.3: CN8.7@50.752,234.946 SB1.2@53.126,234.946
DSI_CK_N: CN10.107 CN19.5 | length 67.4
  Top Layer w0.1: CN19.5@125.25,90.87 125.25,91.889 125.375,92.014 125.375,93.338 126.888,94.852 126.888,95.463 125.708,96.644 125.708,99.377 126.417,100.087 126.417,100.672 126.031,101.057 ; 126.034,101.06 124.734,102.36 124.734,103.09 126.769,105.125 126.769,105.832 125.375,107.226 125.375,145.919 125.375,148.403 126.588,149.616 126.893,149.616 ; 126.893,149.615 129.965,149.615 130.1,149.75 CN10.107@131.13,149.75
DSI_CK_P: CN10.109 CN19.3 | length 67.1
  Top Layer w0.1: CN19.3@125.75,90.87 125.75,91.866 125.605,92.011 125.605,93.243 127.118,94.756 127.118,95.558 125.938,96.739 125.938,99.282 126.647,99.991 126.647,100.798 124.964,102.481 124.964,102.995 126.999,105.03 126.999,105.927 125.605,107.321 125.605,109.485 125.605,148.308 126.682,149.385 129.375,149.385 129.965,149.385 130.1,149.25 CN10.109@131.13,149.25
DSI_D0_N: CN10.103 CN19.11 | length 67.9
  Top Layer w0.1: CN19.11@123.75,90.87 123.75,91.868 123.901,92.019 123.901,99.906 122.127,101.68 122.127,103.57 123.06,104.503 123.06,148.716 124.969,150.626 CN10.103@129.998,150.626 ; CN10.103@129.999,150.624 130.125,150.75 CN10.103@131.13,150.75
DSI_D0_P: CN10.105 CN19.9 | length 67.5
  Top Layer w0.1: CN19.9@124.25,90.87 124.25,91.865 124.131,91.984 124.131,100.001 122.357,101.775 122.357,103.475 123.29,104.407 123.29,148.621 125.044,150.375 130,150.375 130.125,150.25 CN10.105@131.13,150.25
DSI_D1_N: CN10.113 CN19.17 | length 71.1
  Top Layer w0.1: CN19.17@122.25,90.87 122.25,89.874 122.384,89.74 122.384,89.081 122.872,88.594 127.324,88.594 128.962,90.231 128.962,107.858 127.575,109.245 127.575,147.431 128.534,148.39 129.985,148.39 CN10.113@130.023,148.352 ; CN10.113@130.023,148.352 130.125,148.25 CN10.113@131.13,148.25
DSI_D1_P: CN10.111 CN19.15 | length 69.6
  Top Layer w0.1: CN19.15@122.75,90.87 122.75,89.872 122.614,89.736 122.614,89.177 122.967,88.824 127.229,88.824 128.732,90.326 128.732,107.763 127.345,109.15 127.345,110.753 127.345,147.185 127.345,147.527 128.439,148.62 129.99,148.62 CN10.111@130.066,148.696
DSI_RESET: CN9.59 CN19.57 R130.1 | length 103.7
  Top Layer w0.1: CN9.59@61.13,166.75 62.114,166.75 63.083,165.782 63.083,164.551 63.743,163.891 71.259,163.891 93.192,141.958 93.192,109.317 109.484,93.025 ; 109.482,93.025 109.484,93.025 ; CN19.57@112.26,90.836 112.25,90.846 R130.1@112.25,93.025 109.484,93.025
DSI_TE: CN10.117 CN19.49 | length 75.5
  Top Layer w0.1: v1(114.237,101.531) 114.258,101.552 114.258,90.878 CN19.49@114.25,90.87 ; v1(131.096,101.528) 131.098,111.347 129.427,113.018 129.427,146.9 129.777,147.25 CN10.117@131.13,147.25
  Bottom Layer w0.1: v1(114.237,101.531) 131.098,101.531 v1(131.096,101.528)
ETH_CLK: CN9.69 SB23.2 SB77.1 | length 52.1
  Top Layer w0.13: v1(57.824,162.164) 57.817,162.157 SB23.2@57.817,160.998 57.986,160.998 59.734,159.25 CN9.69@61.13,159.25
  Bottom Layer w0.13: SB77.1@17.457,172.209 17.457,168.136 23.429,162.164 v1(57.824,162.164)
ETH_GTX_CLK: CN6.24 CN9.46 U9.34 | length 89.2
  Top Layer w0.13: U9.34@17.425,203.875 17.425,202.47 17.041,202.087 17.041,186.75 17.45,186.342 CN6.24@17.45,182 17.435,181.985 17.56,181.861 17.461,181.762 17.551,181.672 17.448,181.569 v1(17.448,179.021) ; v1(65.26,170.249) 66.869,170.249 CN9.46@66.87,170.25
  Bottom Layer w0.13: v1(17.448,179.021) 17.448,177.095 20.06,174.484 20.06,169.244 22.28,167.024 41.293,167.024 47.624,173.355 48.292,173.355 ; 48.292,173.356 54.885,173.356 59.606,168.636 63.647,168.636 v1(65.26,170.249)
ETH_MDC: CN9.38 R69.1 | length 61.1
  Top Layer w0.1: R69.1@30.187,203.981 30.187,203.897 31.284,202.8 31.284,199.784 v1(30.686,199.186) ; v1(32.818,199.171) 32.818,191.917 42.441,182.294 v1(42.45,182.294) ; v1(65.25,172.239) 66.781,172.239 66.82,172.2 CN9.38@66.87,172.25
  Bottom Layer w0.1: v1(30.686,199.186) 32.832,199.186 v1(32.818,199.171) ; v1(42.45,182.294) 42.431,182.276 42.464,182.243 42.464,175.636 42.994,175.106 56.418,175.106 59.285,172.239 v1(65.25,172.239)
ETH_MDINT: CN6.52 CN9.47 R60.1 U9.56 | length 70.1
  Top Layer w0.1: U9.56@25.075,208.025 25.126,207.974 25.543,207.974 v1(26.025,207.492) 26.552,207.492 R60.1@26.737,207.306 ; v1(30.136,197.667) 30.136,197.641 28.65,196.155 CN6.52@28.65,182 ; v1@42.964,173.911 42.964,176.896 40.484,179.376 29.689,179.376 28.65,180.414 CN6.52@28.65,181.947 ; v1(59.55,169.75) CN9.47@61.13,169.75 ; CN6.52@28.65,181.947 28.624,181.974 CN6.52@28.65,182 ; CN6.52@28.65,181.947 CN6.52@28.65,182
  Bottom Layer w0.1: v1(26.025,207.492) 27.614,205.903 27.614,200.189 v1(30.136,197.667) ; v1@42.927,173.893 55.407,173.893 v1(59.55,169.75)
  other v1: 42.948,173.908
ETH_MDIO: CN9.36 R65.1 | length 60.1
  Top Layer w0.1: R65.1@30.187,205.197 30.624,205.197 32.164,203.657 32.164,191.159 v1(43.258,180.065) ; v1(65.1,173.154) 65.504,172.75 CN9.36@66.87,172.75
  Bottom Layer w0.1: v1(43.258,180.065) 42.9,179.707 42.9,176.4 43.6,175.7 56.828,175.7 59.374,173.154 v1(65.1,173.154)
ETH_RX_CLK: CN9.42 R56.1 | length 109.9
  Top Layer w0.13: v1(11.687,208.137) 12.075,208.525 R56.1@12.875,208.525 ; v1(65.251,171.227) 66.893,171.227 CN9.42@66.87,171.25
  Bottom Layer w0.13: v1(11.687,208.137) 4.54,200.989 4.54,180.571 4.682,180.428 4.684,180.428 5.374,179.738 18.415,179.738 19.086,179.068 19.086,176.447 20.731,174.801 20.731,169.702 22.214,168.219 39.258,168.219 39.563,168.22 41.63,170.287 41.63,173.802 42.335,174.507 55.962,174.507 59.241,171.227 v1(65.251,171.227)
ETH_RX_DV: CN9.60 R38.1 R39.2 R45.1 | length 135
  Top Layer w0.13: v1(8.377,186.048) 8.393,186.063 8.393,205.941 8.254,206.08 8.254,209.379 13.675,214.8 R39.2@14.875,214.8 R45.1@14.875,213.975 ; CN9.60@66.87,166.75 70.392,166.75 77.553,173.911 77.553,186.283 69.561,194.275 v1(69.5,194.275)
  Bottom Layer w0.13: v1(8.377,186.048) 14.015,186.048 22.242,194.275 v1(69.5,194.275)
ETH_RXD0: CN6.4 CN9.58 R48.1 | length 134.3
  Top Layer w0.13: v1(9.784,180.834) 9.685,180.834 9.45,181.069 CN6.4@9.45,182 9.45,185.668 9.455,185.673 9.115,186.014 9.115,209.115 R48.1@12.875,212.875 ; CN9.58@66.87,167.25 70.123,167.25 77.163,174.29 77.163,185.77 69.558,193.375 v1(68.95,193.375)
  Bottom Layer w0.13: v1(9.784,180.834) 22.32,193.37 23.346,193.37 ; 23.346,193.375 v1(68.95,193.375)
ETH_RXD1: CN6.6 CN9.56 R51.1 | length 130.6
  Top Layer w0.13: v1(10.801,180.847) 10.847,180.847 10.877,180.817 10.611,180.817 10.25,181.178 CN6.6@10.25,182 10.25,183.072 10.247,183.074 10.247,185.913 9.557,186.603 9.557,209.004 12.328,211.775 R51.1@12.875,211.775 ; CN9.56@66.87,167.75 69.8,167.75 76.773,174.722 76.773,185.227 73.393,188.607 v1(69.5,192.5)
  Bottom Layer w0.13: v1(10.801,180.847) 22.459,192.505 22.941,192.505 ; 22.941,192.5 v1(69.5,192.5)
ETH_RXD2: CN6.10 CN9.54 R52.1 | length 126.8
  Top Layer w0.13: v1(11.709,180.845) 11.85,180.987 CN6.10@11.85,182 11.85,185.123 10.04,186.933 10.04,208.868 11.708,210.536 12.775,210.536 12.875,210.436 R52.1@12.875,210.675 ; CN9.54@66.87,168.25 69.52,168.25 76.383,175.113 76.383,184.911 72.297,188.998 72.297,189.001 69.598,191.7 v1(68.975,191.7)
  Bottom Layer w0.13: v1(11.709,180.845) 22.284,191.421 68.696,191.421 v1(68.975,191.7)
ETH_RXD3: CN6.12 CN9.52 R55.1 | length 122.9
  Top Layer w0.13: v1(12.643,180.863) 12.65,180.87 CN6.12@12.65,182 12.65,185.238 10.479,187.408 10.479,208.646 11.631,209.798 12.677,209.798 R55.1@12.875,209.6 ; CN9.52@66.87,168.75 69.304,168.75 75.993,175.439 75.993,184.661 72.095,188.559 69.754,190.9 v1(69.5,190.9)
  Bottom Layer w0.13: v1(12.643,180.863) 12.643,180.967 22.575,190.899 22.575,190.9 v1(69.5,190.9)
